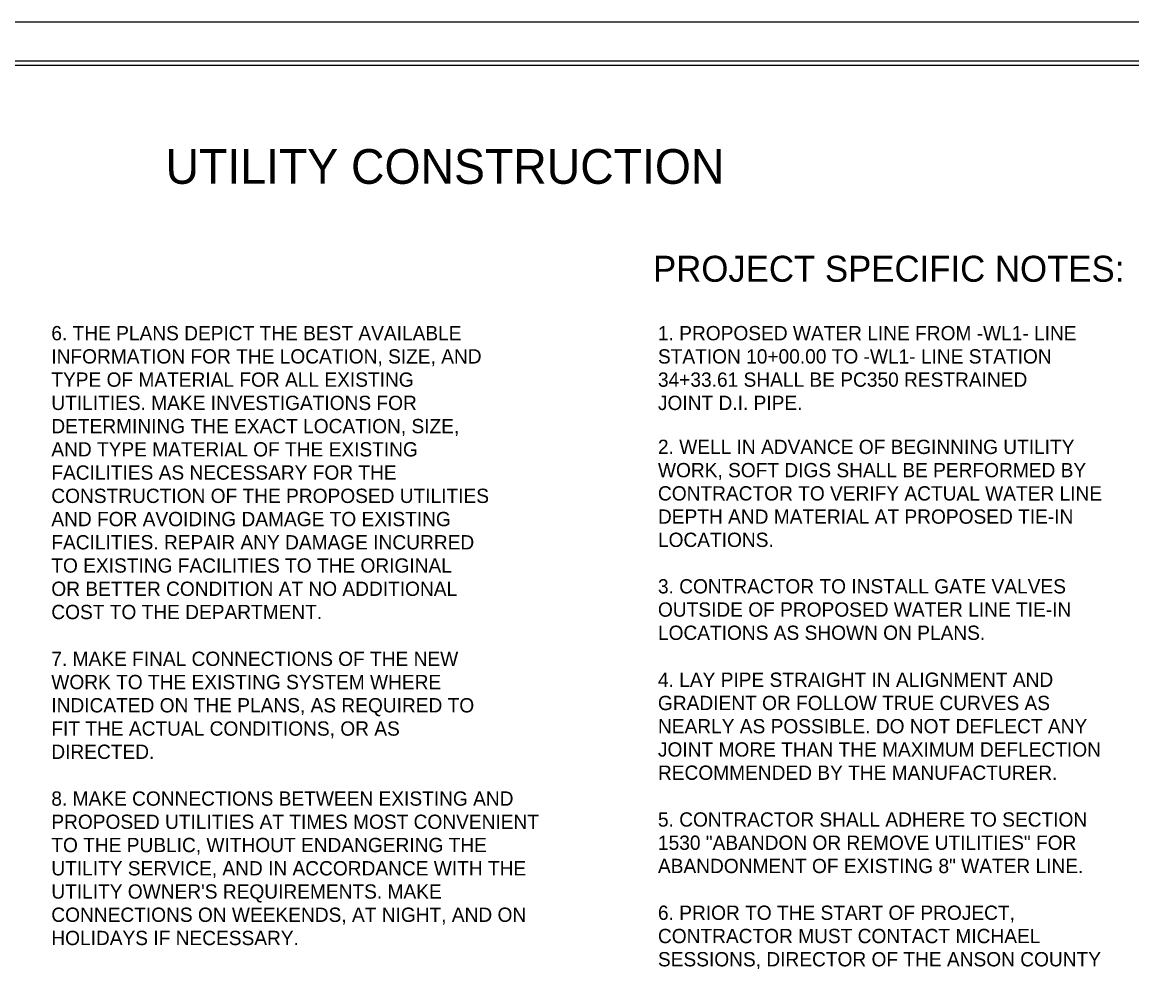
# Model space of a CAD drawing. Extents: x 0 to 674, y 0 to 440.
# Drawn here: x 248.2 to 504.3, y 220.9 to 440 of the extents above; entities that cross this region are included whole.
import ezdxf

# ---------------------------------------------------------------- set-up
doc = ezdxf.new("R2010")
doc.units = 0
for name, color, linetype in [('General Text and Text Box and Leader Line', 7, 'Continuous'), ('Sheet Plot Border Inside CELL', 7, 'Continuous'), ('Sheet Plot Border Outside CELL', 7, 'Continuous'), ('UC Notes and Details Sheet 34 CELL', 7, 'Continuous')]:
    doc.layers.add(name, color=color, linetype=linetype)

msp = doc.modelspace()

# ---------------------------------------------------------------- linework, layer by layer
at = {"layer": 'Sheet Plot Border Inside CELL'}
msp.add_lwpolyline([(671.8, 431.01), (5.2, 431.01), (5.2, 8.97), (671.8, 8.97)], close=True, dxfattribs=at)
at = {"layer": 'Sheet Plot Border Outside CELL'}
msp.add_lwpolyline([(673.6, 440), (0, 440), (0, 0), (673.6, 0)], close=True, dxfattribs=at)
at = {"layer": 'UC Notes and Details Sheet 34 CELL'}
msp.add_lwpolyline([(666.8, 430), (66.8, 430), (66.8, 10), (666.8, 10)], close=True, dxfattribs=at)

# ---------------------------------------------------------------- texts
at = {"layer": 'General Text and Text Box and Leader Line'}
for s, height, p in [('UTILITY CONSTRUCTION', 8, (281.33, 402.7)), ('PROJECT SPECIFIC NOTES:', 6, (393.82, 380.1)), ('6. THE PLANS DEPICT THE BEST AVAILABLE ', 3.3, (254.96, 366.59)), ('1. PROPOSED WATER LINE FROM -WL1- LINE ', 3.3, (394.96, 366.59)), ('INFORMATION FOR THE LOCATION, SIZE, AND ', 3.3, (254.96, 361.23)), ('STATION 10+00.00 TO -WL1- LINE STATION ', 3.3, (394.96, 361.23)), ('TYPE OF MATERIAL FOR ALL EXISTING ', 3.3, (254.96, 355.87)), ('34+33.61 SHALL BE PC350 RESTRAINED ', 3.3, (394.96, 355.87)), ('UTILITIES. MAKE INVESTIGATIONS FOR ', 3.3, (254.96, 350.5)), ('JOINT D.I. PIPE.', 3.3, (394.96, 350.5)), ('DETERMINING THE EXACT LOCATION, SIZE, ', 3.3, (254.96, 345.14)), ('AND TYPE MATERIAL OF THE EXISTING ', 3.3, (254.96, 339.78)), ('FACILITIES AS NECESSARY FOR THE ', 3.3, (254.96, 334.42)), ('CONSTRUCTION OF THE PROPOSED UTILITIES ', 3.3, (254.96, 329.05)), ('AND FOR AVOIDING DAMAGE TO EXISTING ', 3.3, (254.96, 323.69)), ('FACILITIES. REPAIR ANY DAMAGE INCURRED ', 3.3, (254.96, 318.33)), ('TO EXISTING FACILITIES TO THE ORIGINAL ', 3.3, (254.96, 312.97)), ('OR BETTER CONDITION AT NO ADDITIONAL ', 3.3, (254.96, 307.6)), ('COST TO THE DEPARTMENT.', 3.3, (254.96, 302.24)), ('7. MAKE FINAL CONNECTIONS OF THE NEW ', 3.3, (254.96, 291.44)), ('WORK TO THE EXISTING SYSTEM WHERE ', 3.3, (254.96, 286.08)), ('4. LAY PIPE STRAIGHT IN ALIGNMENT AND ', 3.3, (394.96, 286.61)), ('GRADIENT OR FOLLOW TRUE CURVES AS ', 3.3, (394.96, 281.25)), ('INDICATED ON THE PLANS, AS REQUIRED TO ', 3.3, (254.96, 280.72)), ('NEARLY AS POSSIBLE. DO NOT DEFLECT ANY ', 3.3, (394.96, 275.89)), ('FIT THE ACTUAL CONDITIONS, OR AS ', 3.3, (254.96, 275.35)), ('DIRECTED.', 3.3, (254.96, 269.99)), ('JOINT MORE THAN THE MAXIMUM DEFLECTION ', 3.3, (394.96, 270.52)), ('RECOMMENDED BY THE MANUFACTURER.', 3.3, (394.96, 265.16)), ('8. MAKE CONNECTIONS BETWEEN EXISTING AND ', 3.3, (254.96, 259.19)), ('PROPOSED UTILITIES AT TIMES MOST CONVENIENT ', 3.3, (254.96, 253.83)), ('5. CONTRACTOR SHALL ADHERE TO SECTION ', 3.3, (394.96, 254.36)), ('TO THE PUBLIC, WITHOUT ENDANGERING THE ', 3.3, (254.96, 248.47)), ('1530 "ABANDON OR REMOVE UTILITIES" FOR ', 3.3, (394.96, 249)), ('UTILITY SERVICE, AND IN ACCORDANCE WITH THE ', 3.3, (254.96, 243.1)), ('ABANDONMENT OF EXISTING 8" WATER LINE.', 3.3, (394.96, 243.64)), ("UTILITY OWNER'S REQUIREMENTS. MAKE ", 3.3, (254.96, 237.74)), ('CONNECTIONS ON WEEKENDS, AT NIGHT, AND ON ', 3.3, (254.96, 232.38)), ('6. PRIOR TO THE START OF PROJECT, ', 3.3, (394.96, 232.84)), ('CONTRACTOR MUST CONTACT MICHAEL ', 3.3, (394.96, 227.47)), ('HOLIDAYS IF NECESSARY.', 3.3, (254.96, 227.02)), ('SESSIONS, DIRECTOR OF THE ANSON COUNTY ', 3.3, (394.96, 222.11))]:
    msp.add_text(s, height=height, rotation=360, dxfattribs=at).set_placement(p)
for s, p in [('2. WELL IN ADVANCE OF BEGINNING UTILITY ', (394.96, 340.35)), ('WORK, SOFT DIGS SHALL BE PERFORMED BY ', (394.96, 334.98)), ('CONTRACTOR TO VERIFY ACTUAL WATER LINE ', (394.96, 329.62)), ('DEPTH AND MATERIAL AT PROPOSED TIE-IN ', (394.96, 324.26)), ('LOCATIONS.', (394.96, 318.9)), ('3. CONTRACTOR TO INSTALL GATE VALVES ', (394.96, 308.17)), ('OUTSIDE OF PROPOSED WATER LINE TIE-IN ', (394.96, 302.81)), ('LOCATIONS AS SHOWN ON PLANS.', (394.96, 297.45))]:
    msp.add_text(s, height=3.3, dxfattribs=at).set_placement(p)

doc.saveas('drawing.dxf')
